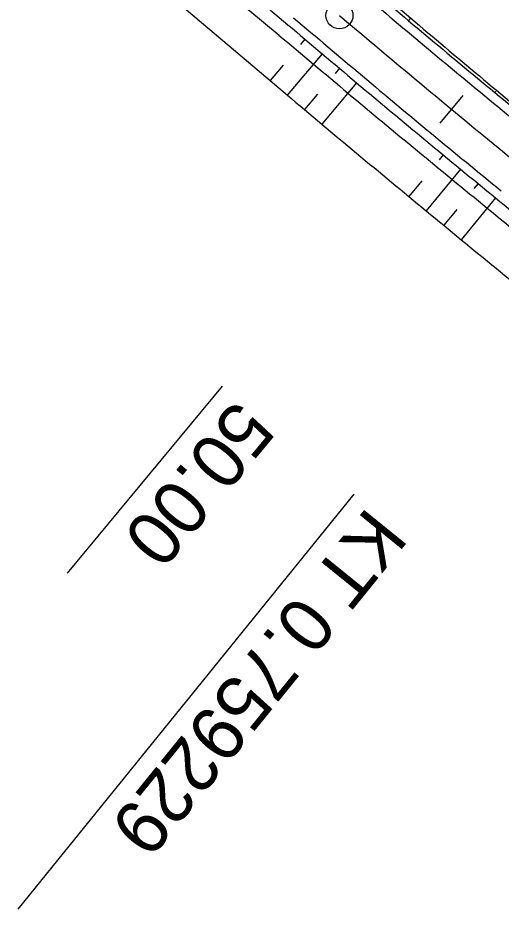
# Model space of a CAD drawing. Extents: x -481645 to -478728, y -1113199 to -1110710.
# Drawn here: x -481200.49 to -481173.62, y -1113146.51 to -1113096.94 of the extents above; entities that cross this region are included whole.
import ezdxf

# ---------------------------------------------------------------- set-up
doc = ezdxf.new("R2010")
doc.units = 0
for name, color, linetype in [('Vrstva 41', 7, 'Continuous'), ('Vrstva 42', 7, 'Continuous'), ('Vrstva 43', 7, 'Continuous'), ('Vrstva 44', 7, 'Continuous'), ('Vrstva 45', 7, 'Continuous'), ('Vrstva 46', 7, 'Continuous'), ('Vrstva 47', 7, 'Continuous'), ('Vrstva 48', 7, 'Continuous'), ('Vrstva 50', 7, 'Continuous'), ('Vrstva 51', 7, 'Continuous')]:
    doc.layers.add(name, color=color, linetype=linetype)

msp = doc.modelspace()

# ---------------------------------------------------------------- linework, layer by layer
at = {"layer": 'Vrstva 41'}
msp.add_arc((-480665.956, -1112486.009), 800, 229.772939, 231.016817, dxfattribs=at)
at = {"layer": 'Vrstva 42'}
msp.add_line((-481191.242, -1113096.382), (-481187.425, -1113099.612), dxfattribs=at)
for centre, radius, start, end in [((-479626.705, -1111275.844), 2392.69, 229.443117, 229.562619), ((-480662.911, -1112488.56), 797.576, 229.712358, 230.070464), ((-479627.561, -1111254.957), 2415.766, 229.7817, 229.900778), ((-480663.631, -1112487.93), 797.598, 230.139183, 230.497286), ((-480666.373, -1112485.661), 805.254, 230.036411, 230.394511), ((-480665.303, -1112486.546), 805.255, 230.295675, 230.653775), ((-480919.603, -1112798.704), 402.629, 230.47549, 231.19098)]:
    msp.add_arc(centre, radius, start, end, dxfattribs=at)
at = {"layer": 'Vrstva 43'}
msp.add_line((-481189.795, -1113094.671), (-481185.972, -1113097.894), dxfattribs=at)
for centre, radius, start, end in [((-479633.34, -1111255.998), 2408.993, 229.870675, 229.989875), ((-480666.892, -1112485.229), 802.994, 230.084642, 230.442742), ((-480666.893, -1112485.238), 802.986, 230.442394, 230.800494), ((-480919.655, -1112797.189), 401.491, 230.61752, 231.33331)]:
    msp.add_arc(centre, radius, start, end, dxfattribs=at)
at = {"layer": 'Vrstva 44'}
msp.add_line((-481189.302, -1113094.088), (-481185.485, -1113097.317), dxfattribs=at)
for centre, radius, start, end in [((-479637.316, -1111266.367), 2393.25, 229.783661, 229.903153), ((-479631.514, -1111259.487), 2406.75, 229.783933, 229.903175), ((-480665.956, -1112486.009), 797.75, 229.997717, 230.355817), ((-480665.956, -1112486.009), 797.75, 230.355817, 230.713917), ((-480665.956, -1112486.009), 802.25, 229.997717, 230.355817), ((-480665.956, -1112486.009), 802.25, 230.355817, 230.713917), ((-480918.954, -1112797.291), 401.125, 230.53069, 231.24658)]:
    msp.add_arc(centre, radius, start, end, dxfattribs=at)
at = {"layer": 'Vrstva 45'}
for centre, radius, start, end in [((-479636.671, -1111265.603), 2394.75, 229.783692, 229.903156), ((-479632.159, -1111260.251), 2405.25, 229.783903, 229.903172), ((-480665.956, -1112486.009), 798.25, 229.997717, 230.355817), ((-480665.956, -1112486.009), 801.75, 229.997717, 230.355817), ((-480665.956, -1112486.009), 798.25, 230.355817, 230.713917), ((-480665.956, -1112486.009), 801.75, 230.355817, 230.713917)]:
    msp.add_arc(centre, radius, start, end, dxfattribs=at)
at = {"layer": 'Vrstva 46'}
for centre, radius, start, end in [((-479636.671, -1111265.603), 2394.75, 229.783692, 229.903156), ((-479632.159, -1111260.251), 2405.25, 229.783903, 229.903172), ((-480665.956, -1112486.009), 798.25, 229.997717, 230.355817), ((-480665.956, -1112486.009), 801.75, 229.997717, 230.355817), ((-480665.956, -1112486.009), 798.25, 230.355817, 230.713917), ((-480665.956, -1112486.009), 801.75, 230.355817, 230.713917)]:
    msp.add_arc(centre, radius, start, end, dxfattribs=at)
at = {"layer": 'Vrstva 47'}
for p, q in [((-481177.008, -1113102.796), (-481175.732, -1113101.256)), ((-481189.13, -1113117.426), (-481197.744, -1113127.822))]:
    msp.add_line(p, q, dxfattribs=at)
at = {"layer": 'Vrstva 48'}
msp.add_line((-481181.811, -1113123.42), (-481200.495, -1113146.507), dxfattribs=at)
msp.add_circle((-481182.61, -1113096.802), 0.75, dxfattribs=at)
at = {"layer": 'Vrstva 50'}
for p, q in [((-481178.764, -1113097.1), (-481178.644, -1113096.957)), ((-481173.974, -1113101.088), (-481173.924, -1113101.028)), ((-481173.874, -1113100.967), (-481173.874, -1113100.967))]:
    msp.add_line(p, q, dxfattribs=at)
at = {"layer": 'Vrstva 51'}
for p, q in [((-481184.53, -1113098.124), (-481184.774, -1113098.412)), ((-481183.574, -1113098.933), (-481185.513, -1113101.229)), ((-481185.744, -1113099.56), (-481186.471, -1113100.419)), ((-481182.616, -1113099.741), (-481182.857, -1113100.028)), ((-481181.656, -1113100.547), (-481183.588, -1113102.849)), ((-481183.825, -1113101.177), (-481184.551, -1113102.04)), ((-481176.84, -1113104.557), (-481177.075, -1113104.842)), ((-481175.873, -1113105.355), (-481177.782, -1113107.674)), ((-481178.031, -1113106), (-481178.752, -1113106.873)), ((-481174.904, -1113106.151), (-481175.137, -1113106.435)), ((-481173.935, -1113106.945), (-481175.839, -1113109.273)), ((-481176.09, -1113107.596), (-481176.811, -1113108.474))]:
    msp.add_line(p, q, dxfattribs=at)

# ---------------------------------------------------------------- texts
at = {"layer": 'Vrstva 47'}
msp.add_text('50.00', height=3, rotation=230.3558, dxfattribs=at).set_placement((-481188.36, -1113118.064))
at = {"layer": 'Vrstva 48'}
msp.add_text('KT 0.759229', height=2.999, rotation=231.0168, dxfattribs=at).set_placement((-481181.033, -1113124.048))

doc.saveas('drawing.dxf')
